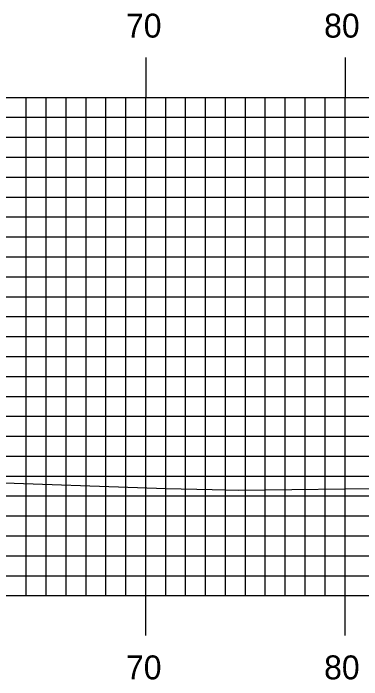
# Model space of a CAD drawing. Extents: x 856323 to 856666, y 364765 to 364985.
# Drawn here: x 856552.12 to 856569.6, y 364824.09 to 364857.52 of the extents above; entities that cross this region are included whole.
import ezdxf

# ---------------------------------------------------------------- set-up
doc = ezdxf.new("R2010")
doc.units = 0
for name, color, linetype in [('H_V ANNOTATION', 7, 'Continuous'), ('MAJOR', 7, 'Continuous'), ('MINOR', 7, 'Continuous'), ('S_Roadway_Centerline', 7, 'Continuous')]:
    doc.layers.add(name, color=color, linetype=linetype)

msp = doc.modelspace()

# ---------------------------------------------------------------- linework, layer by layer
at = {"layer": 'MAJOR'}
for p, q in [((856558.768, 364855.306), (856558.768, 364853.302)), ((856568.768, 364855.306), (856568.768, 364853.302)), ((856348.768, 364853.302), (856628.768, 364853.302)), ((856348.768, 364853.302), (856628.768, 364853.302)), ((856558.768, 364828.302), (856558.768, 364853.302)), ((856568.768, 364828.302), (856568.768, 364853.302)), ((856348.768, 364848.302), (856628.768, 364848.302)), ((856348.768, 364843.302), (856628.768, 364843.302)), ((856348.768, 364838.302), (856628.768, 364838.302)), ((856348.768, 364833.302), (856628.768, 364833.302)), ((856348.768, 364828.302), (856628.768, 364828.302)), ((856348.768, 364828.302), (856628.768, 364828.302)), ((856558.768, 364826.298), (856558.768, 364828.302)), ((856568.768, 364826.298), (856568.768, 364828.302))]:
    msp.add_line(p, q, dxfattribs=at)
at = {"layer": 'MINOR'}
for p, q in [((856552.768, 364828.302), (856552.768, 364853.302)), ((856553.768, 364828.302), (856553.768, 364853.302)), ((856554.768, 364828.302), (856554.768, 364853.302)), ((856555.768, 364828.302), (856555.768, 364853.302)), ((856556.768, 364828.302), (856556.768, 364853.302)), ((856557.768, 364828.302), (856557.768, 364853.302)), ((856559.768, 364828.302), (856559.768, 364853.302)), ((856560.768, 364828.302), (856560.768, 364853.302)), ((856561.768, 364828.302), (856561.768, 364853.302)), ((856562.768, 364828.302), (856562.768, 364853.302)), ((856563.768, 364828.302), (856563.768, 364853.302)), ((856564.768, 364828.302), (856564.768, 364853.302)), ((856565.768, 364828.302), (856565.768, 364853.302)), ((856566.768, 364828.302), (856566.768, 364853.302)), ((856567.768, 364828.302), (856567.768, 364853.302)), ((856348.768, 364852.302), (856628.768, 364852.302)), ((856348.768, 364851.302), (856628.768, 364851.302)), ((856348.768, 364850.302), (856628.768, 364850.302)), ((856348.768, 364849.302), (856628.768, 364849.302)), ((856348.768, 364847.302), (856628.768, 364847.302)), ((856348.768, 364846.302), (856628.768, 364846.302)), ((856348.768, 364845.302), (856628.768, 364845.302)), ((856348.768, 364844.302), (856628.768, 364844.302)), ((856348.768, 364842.302), (856628.768, 364842.302)), ((856348.768, 364841.302), (856628.768, 364841.302)), ((856348.768, 364840.302), (856628.768, 364840.302)), ((856348.768, 364839.302), (856628.768, 364839.302)), ((856348.768, 364837.302), (856628.768, 364837.302)), ((856348.768, 364836.302), (856628.768, 364836.302)), ((856348.768, 364835.302), (856628.768, 364835.302)), ((856348.768, 364834.302), (856628.768, 364834.302)), ((856348.768, 364832.302), (856628.768, 364832.302)), ((856348.768, 364831.302), (856628.768, 364831.302)), ((856348.768, 364830.302), (856628.768, 364830.302)), ((856348.768, 364829.302), (856628.768, 364829.302))]:
    msp.add_line(p, q, dxfattribs=at)
at = {"layer": 'S_Roadway_Centerline'}
msp.add_lwpolyline([(856468.17, 364834.44), (856477.631, 364834.392), (856488.091, 364834.229), (856493.984, 364834.166), (856502.233, 364834.138), (856506.394, 364834.174), (856523.832, 364834.442), (856525.471, 364834.453), (856525.841, 364834.454), (856526.497, 364834.44), (856538.058, 364834.187), (856544.846, 364834.073), (856550.24, 364834.018), (856559.769, 364833.685), (856562.105, 364833.634), (856563.443, 364833.597), (856571.424, 364833.699)], dxfattribs=at)

# ---------------------------------------------------------------- texts
at = {"layer": 'H_V ANNOTATION'}
for s, p in [('70', (856557.773, 364856.302)), ('80', (856567.719, 364856.302)), ('70', (856557.773, 364824.102)), ('80', (856567.719, 364824.102))]:
    msp.add_text(s, height=1.2, dxfattribs=at).set_placement(p)

doc.saveas('drawing.dxf')
